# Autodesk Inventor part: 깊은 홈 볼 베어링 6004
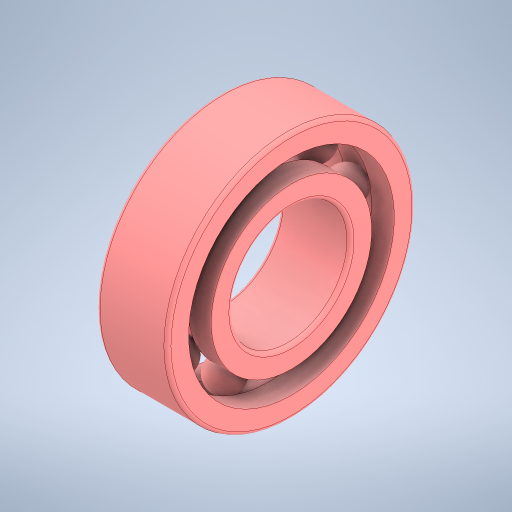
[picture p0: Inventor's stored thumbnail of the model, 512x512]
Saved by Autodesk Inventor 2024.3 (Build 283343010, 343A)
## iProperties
Created: 2025-11
Part Number: 깊은 홈 볼 베어링 6004
Material: 강철, 연강
Description: 깊은 그루브 볼 베어링
Document SubType Name: Modeling
Designer: PC2-15
Density: 7.85 g/cm^3
Appearance: 기본값
Author: jhkim
Sending System: Autodesk Inventor 2026
Preprocessor: ST-DEVELOPER v20.1
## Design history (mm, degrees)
node "깊은 홈 볼 베어링 60041"
node "솔리드1"
node "솔리드2"
node "솔리드3"
node "솔리드4"
node "솔리드5"
node "솔리드6"
node "솔리드7"
node "솔리드8"
node "솔리드9"
node "솔리드10"
node "솔리드11"
body "Solid1"
node "Solid1:1"
node "Solid1:2"
node "Solid1:3"
node "Solid1:4"
node "Solid1:5"
node "Solid1:6"
node "Solid1:7"
node "Solid1:8"
node "Solid1:9"
node "Solid1:10"
